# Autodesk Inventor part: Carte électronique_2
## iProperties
Created: 2010-07
Part Number: Carte électronique_2
Document SubType Name: Modeling
Designer: eric
Density: 1 g/cm^3
Author: eric
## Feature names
1. Base1
